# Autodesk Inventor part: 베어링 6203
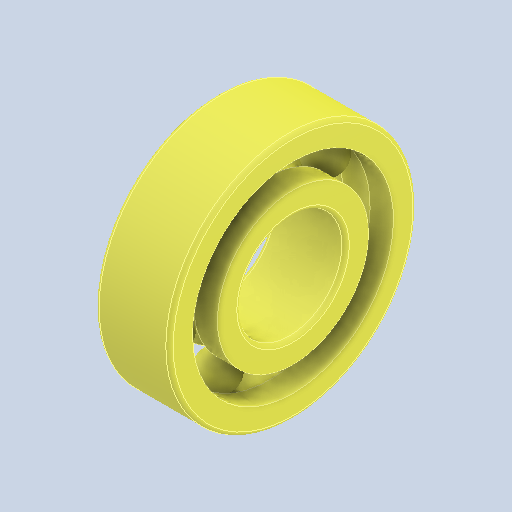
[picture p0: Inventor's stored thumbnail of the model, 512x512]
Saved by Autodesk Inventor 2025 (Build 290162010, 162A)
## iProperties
Created: 2024-07
Part Number: 베어링 6203
Material: 강철, 연강
Description: 깊은 그루브 볼 베어링
Document SubType Name: Modeling
Designer: 학생
Density: 7.86 g/cm^3
Appearance: 기본값
Author: jhkim
Revision Number: 1
Sending System: Autodesk Inventor 2025
Preprocessor: ST-DEVELOPER v20
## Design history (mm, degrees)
feature "Solid1"
feature "Solid1:1"
feature "Solid1:2"
feature "Solid1:3"
feature "Solid1:4"
feature "Solid1:5"
feature "Solid1:6"
feature "Solid1:7"
feature "Solid1:8"
node "솔리드1"
node "솔리드2"
node "솔리드3"
node "솔리드4"
node "솔리드5"
node "솔리드6"
node "솔리드7"
node "솔리드8"
node "솔리드9"
